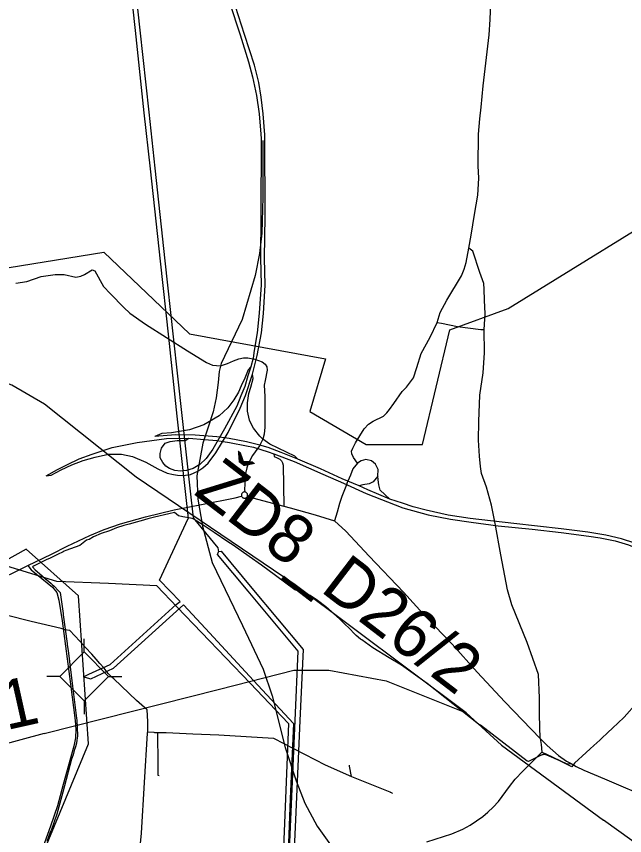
# Model space of a CAD drawing. Extents: x -789162 to -606354, y -1062736 to -945481.
# Drawn here: x -686768 to -684895, y -994659 to -992137 of the extents above; entities that cross this region are included whole.
import ezdxf

# ---------------------------------------------------------------- set-up
doc = ezdxf.new("R2010")
doc.units = 0
for name, color, linetype in [('_SIRSI VZTAHY_CYKLOTRASY MISTNI S', 7, 'Continuous'), ('_SIRSI VZTAHY_ELEKTRICKE VEDENI VN 110 kV S', 7, 'Continuous'), ('_SIRSI VZTAHY_ELEKTRO_ROZVODNA S', 7, 'Continuous'), ('_SIRSI VZTAHY_OP vodnich zdroju II stupne', 7, 'Continuous'), ('_SIRSI VZTAHY_SILNICE I TRIDY_NAVRH', 7, 'Continuous'), ('_SIRSI VZTAHY_SILNICE I TRIDY_STAV', 7, 'Continuous'), ('_SIRSI VZTAHY_SILNICE II TRIDY_STAV', 7, 'Continuous'), ('_SIRSI VZTAHY_SILNICE III TRIDY_STAV', 7, 'Continuous'), ('_SIRSI VZTAHY_VTL PLYNOVOD', 7, 'Continuous'), ('_SIRSI VZTAHY_ZELEZNICE NAVRH', 7, 'Continuous'), ('_SIRSI VZTAHY_ZELEZNICE_NAVRH POPIS', 7, 'Continuous')]:
    doc.layers.add(name, color=color, linetype=linetype)

msp = doc.modelspace()

# ---------------------------------------------------------------- linework, layer by layer
at = {"layer": '_SIRSI VZTAHY_CYKLOTRASY MISTNI S'}
for points in [[(-687456.1, -993024.3), (-687013.2, -992946.4), (-686498.6, -992862.6), (-686235.3, -993114.1), (-685816.3, -993191.9), (-685864.2, -993353.6), (-685690.7, -993455.4), (-685517.1, -993455.4), (-685433.3, -993102.1), (-685253.8, -993036.2), (-684661.3, -992670.9), (-684535.6, -992790.7), (-683781.6, -992335.6), (-683775.6, -992760.8), (-683195.1, -992383.5), (-682889.9, -992994.3), (-682866, -992760.8)], [(-684053.5, -995624.9), (-684491.2, -995009), (-684778.4, -995050.1), (-684949.4, -994827.6), (-685034.9, -995207.5), (-685534.2, -995217.7), (-685623.1, -994998.7), (-686119, -994820.8), (-686426.8, -994858.4), (-686720.9, -994796.8), (-686546.4, -994375.9), (-686577.2, -993920.8), (-686738, -993777.1), (-687381.5, -994136), (-687477.3, -993800.6), (-687483.2, -993028.1)]]:
    msp.add_lwpolyline(points, dxfattribs=at)
at = {"layer": '_SIRSI VZTAHY_ELEKTRICKE VEDENI VN 110 kV S'}
for points in [[(-686349, -990126), (-686423, -990349.7), (-686497.1, -990573.9), (-686557.7, -990757.1), (-686529.4, -991016.9), (-686502.4, -991265.1), (-686475.3, -991514.4), (-686450, -991747.7), (-686425.4, -991973.3), (-686402.7, -992181.3), (-686375.2, -992433.8), (-686356.6, -992606.6), (-686325.5, -992891.3), (-686300.1, -993125.2), (-686273.7, -993367.7), (-686249.4, -993590.9)], [(-686349, -990126), (-686423, -990349.7), (-686497.1, -990573.9), (-686557.7, -990757.1), (-686529.4, -991016.9), (-686502.4, -991265.1), (-686475.3, -991514.4), (-686450, -991747.7), (-686425.4, -991973.3), (-686402.7, -992181.3), (-686375.2, -992433.8), (-686356.6, -992606.6), (-686325.5, -992891.3), (-686300.1, -993125.2), (-686273.7, -993367.7), (-686249.4, -993590.9)], [(-686334.7, -990130.7), (-686408.7, -990354.4), (-686482.9, -990578.6), (-686542.4, -990758.7), (-686514.5, -991015.2), (-686487.5, -991263.5), (-686460.4, -991512.7), (-686435, -991746), (-686410.4, -991971.7), (-686387.8, -992179.6), (-686360.3, -992432.1), (-686341.6, -992605), (-686310.6, -992889.6), (-686285.2, -993123.6), (-686258.8, -993366.1), (-686234.5, -993589.2)], [(-686334.7, -990130.7), (-686408.7, -990354.4), (-686482.9, -990578.6), (-686542.4, -990758.7), (-686514.5, -991015.2), (-686487.5, -991263.5), (-686460.4, -991512.7), (-686435, -991746), (-686410.4, -991971.7), (-686387.8, -992179.6), (-686360.3, -992432.1), (-686341.6, -992605), (-686310.6, -992889.6), (-686285.2, -993123.6), (-686258.8, -993366.1), (-686234.5, -993589.2)], [(-686249.4, -993590.9), (-686239.2, -993682.7)], [(-686234.5, -993589.2), (-686224.3, -993681)], [(-686327.6, -993873), (-686239.2, -993682.7)], [(-686224.3, -993681), (-686147.6, -993772.6), (-686145.8, -993785.2)], [(-686335.6, -993890.5), (-686484.1, -993882.5), (-686643.8, -993877.1), (-686878.4, -993804.9), (-687098.1, -993735.7)], [(-684808.5, -995839.1), (-685038.4, -995799.1), (-685278, -995757.4), (-685386.1, -995738.6), (-685515, -995521.3), (-685674.8, -995252.1), (-685803.8, -995034.6), (-685932.5, -994817.9), (-685922.3, -994585.9), (-685909.9, -994304.2), (-685900.6, -994091.1), (-686054.2, -993906.6), (-686148.6, -993793.5), (-686145.8, -993785.2)], [(-684808.5, -995839.1), (-685038.4, -995799.1), (-685278, -995757.4), (-685386.1, -995738.6), (-685515, -995521.3), (-685674.8, -995252.1), (-685803.8, -995034.6), (-685932.5, -994817.9), (-685922.3, -994585.9), (-685909.9, -994304.2), (-685900.6, -994091.1), (-686054.2, -993906.6), (-686148.6, -993793.5), (-686145.8, -993785.2)], [(-686144.4, -993784.8), (-686137.8, -993783), (-686042.7, -993897), (-685885.3, -994086.1), (-685894.9, -994304.9), (-685907.3, -994586.4), (-685917.4, -994814), (-685790.9, -995026.9), (-685661.9, -995244.4), (-685502.1, -995513.6), (-685376.7, -995725), (-685275.7, -995742.5), (-685035.9, -995784.3), (-684805.8, -995824.3)], [(-686144.4, -993784.8), (-686137.8, -993783), (-686042.7, -993897), (-685885.3, -994086.1), (-685894.9, -994304.9), (-685907.3, -994586.4), (-685917.4, -994814), (-685790.9, -995026.9), (-685661.9, -995244.4), (-685502.1, -995513.6), (-685376.7, -995725), (-685275.7, -995742.5), (-685035.9, -995784.3), (-684805.8, -995824.3)], [(-686335.6, -993890.5), (-686272.8, -993955.9), (-686198.4, -994034), (-686048.5, -994189.7), (-685930.6, -994313.4)], [(-686327.6, -993873), (-686263.8, -993937.8)], [(-686558.6, -994170), (-686558.6, -994169.6), (-686559.2, -994169.6), (-686559.2, -994168.9), (-686544.8, -994162.2), (-686479.6, -994131.8), (-686275.9, -993948), (-686263.8, -993937.8)], [(-686558.6, -994170), (-686558.6, -994169.7), (-686559.2, -994169.7), (-686559.2, -994170.7), (-686557.8, -994170.7), (-686538.5, -994175.9), (-686469.5, -994143), (-686253.7, -993948.4)], [(-686253.7, -993948.4), (-686186.2, -994021.8), (-686037.9, -994181.8), (-685915.3, -994313.6)], [(-685930.6, -994313.4), (-685939.6, -994544.9), (-685950.8, -994822.5), (-685836.9, -995016.8), (-685710.8, -995231.7), (-685573.2, -995464.2), (-685438.6, -995695.3), (-685306.4, -995922.2), (-685024.6, -995974.9), (-684755, -996025.3)], [(-685915.3, -994313.6), (-685924.6, -994545.5), (-685935.6, -994818.7), (-685824, -995009.2), (-685697.8, -995224.1), (-685560.3, -995456.6), (-685425.6, -995687.8), (-685296.9, -995908.7), (-685021.9, -995960.1), (-684752.2, -996010.5)]]:
    msp.add_lwpolyline(points, dxfattribs=at)
at = {"layer": '_SIRSI VZTAHY_ELEKTRO_ROZVODNA S'}
for p, q in [((-686559.2, -994093.6), (-686559.2, -994053.2)), ((-686634.5, -994168.9), (-686559.2, -994093.6)), ((-686559.2, -994093.6), (-686484, -994168.9)), ((-686634.5, -994168.9), (-686674.9, -994168.9)), ((-686559.2, -994244.1), (-686634.5, -994168.9)), ((-686484, -994168.9), (-686559.2, -994244.1)), ((-686484, -994168.9), (-686443.5, -994168.9)), ((-686559.2, -994244.1), (-686559.2, -994284.6))]:
    msp.add_line(p, q, dxfattribs=at)
at = {"layer": '_SIRSI VZTAHY_OP vodnich zdroju II stupne'}
msp.add_lwpolyline([(-684856.5, -994248.7), (-684896.3, -994293.8), (-684916, -994312.7), (-684931.6, -994327.4), (-684947.5, -994342.4), (-684965.4, -994358.8), (-684971.6, -994364.7), (-684990, -994381.5), (-685000.8, -994391.5), (-685013.5, -994402.9), (-685049.3, -994435.8), (-685057.4, -994447.2), (-685086.6, -994432.4), (-685096.7, -994427.8), (-685134.6, -994411.1), (-685136.1, -994410.5), (-685137.7, -994410), (-685139.3, -994409.6), (-685140.9, -994409.4), (-685142.6, -994409.3), (-685144.2, -994409.3), (-685145.8, -994409.5), (-685147.4, -994409.8), (-685149.3, -994410.2), (-685151, -994410.7), (-685152.7, -994411.4), (-685154.3, -994412.2), (-685155.8, -994413.1), (-685191.4, -994430.8), (-685194.9, -994429.2), (-685339.3, -994319.2), (-685345.4, -994316.3), (-685503.2, -994190.7), (-685581.8, -994134.5), (-685620.5, -994111.4), (-685670.4, -994081.1), (-685704.4, -994056.7), (-685708.2, -994053.9), (-685721.4, -994042.4), (-685729.3, -994035.6), (-685740.5, -994023.7), (-685759.8, -994005.2), (-685771.2, -993993.3), (-685782.5, -993983.8), (-685789.2, -993977.5), (-685815, -993954.4), (-685840.7, -993935.5), (-685863.3, -993920.2), (-685889.8, -993908.5), (-685910.7, -993902.6), (-685970.4, -993858.7), (-686013.3, -993826.4), (-686051.4, -993799.6), (-686100.6, -993765.2), (-686116.6, -993754.5), (-686159.5, -993725.8), (-686193, -993703.5), (-686224.1, -993683.5), (-686231.8, -993681.7), (-686255.1, -993677.2), (-686268.9, -993675), (-686280.8, -993664.2), (-686299.2, -993668.3), (-686342.7, -993678.5), (-686363.2, -993684.1), (-686384.2, -993689.5), (-686398.9, -993693.6), (-686402.9, -993694.8), (-686421, -993699.8), (-686437.1, -993704.5), (-686440.4, -993705.5), (-686457, -993710.1), (-686459.4, -993711.2), (-686481.5, -993720.9), (-686506.7, -993728.8), (-686530.4, -993739.3), (-686543.7, -993747.7), (-686552.3, -993749.7), (-686562.7, -993758), (-686572.3, -993765.7), (-686616, -993781), (-686621.4, -993783.6), (-686624.6, -993785.2), (-686641.5, -993793.5), (-686664.3, -993804.6), (-686676.2, -993810.5), (-686715.9, -993829.9), (-686718.7, -993831.3), (-686710.6, -993841), (-686689.6, -993858.7), (-686685.6, -993862.1), (-686662.5, -993881.7), (-686658.1, -993886.2), (-686651.9, -993890.6), (-686638.6, -993905.8), (-686633.5, -993910.5), (-686624.5, -993975.4), (-686624.1, -993978.8), (-686611.9, -994067.1), (-686611.3, -994071.6), (-686608.6, -994089.3), (-686595.1, -994198.9), (-686586, -994272.7), (-686582.9, -994297.2), (-686582.2, -994303.2), (-686582, -994310.8), (-686581.7, -994313.5), (-686581, -994316.7), (-686580.8, -994327.1), (-686580.8, -994329.3), (-686580.4, -994347.4), (-686580.2, -994353.1), (-686582, -994365.3), (-686583.3, -994374.4), (-686586.4, -994385.3), (-686589.8, -994397.1), (-686593.8, -994410.1), (-686598, -994423.7), (-686619.7, -994505.9), (-686624.8, -994525.2), (-686634.5, -994559.2), (-686643.1, -994592.4), (-686660.8, -994642.7), (-686664, -994648.5), (-686674.9, -994676.4)], dxfattribs=at)
at = {"layer": '_SIRSI VZTAHY_SILNICE I TRIDY_NAVRH'}
msp.add_lwpolyline([(-686009, -992519.3), (-686008.8, -992693.9), (-686012.4, -992805), (-686019.8, -992867), (-686033.1, -992934.5), (-686072.5, -993070.3), (-686127.1, -993184), (-686137.7, -993205.4), (-686143.7, -993230), (-686147.2, -993264.3), (-686152.7, -993311.3), (-686161.7, -993354.7), (-686177.9, -993402), (-686193.9, -993451), (-686212.2, -993551.1), (-686209.7, -993623.7), (-686195.4, -993706.4), (-686165.2, -993818.4), (-686071.8, -994012.5), (-686008, -994147), (-685980.1, -994228.6), (-685940.6, -994387.4), (-685906.2, -994489.7), (-685880.1, -994559.2), (-685841.6, -994630.1), (-685780.6, -994715.4)], dxfattribs=at)
at = {"layer": '_SIRSI VZTAHY_SILNICE I TRIDY_STAV'}
for points in [[(-686371.7, -991297.6), (-686361.9, -991326.8), (-686255.6, -991648.6), (-686175.5, -991900.5), (-686079.2, -992193.9), (-686053, -992277.8), (-686041, -992323), (-686028.4, -992380.7), (-686020.2, -992437.3), (-686015.1, -992500.1), (-686014.6, -992512.8)], [(-686002.6, -992506.4), (-686002.8, -992501.9), (-686008.2, -992437.6), (-686014.5, -992385.9), (-686022, -992341.3), (-686034.7, -992287.1), (-686065.4, -992192.7), (-686158.5, -991904.8), (-686243.5, -991648.6), (-686361.2, -991289.1)], [(-686040.9, -993238.6), (-686027.2, -993181.1), (-686013.8, -993111.8), (-686007.3, -993051.8), (-686001.8, -992964.6), (-686003.8, -992881.1), (-686002.4, -992753.1), (-686002.6, -992506.4)], [(-686014.6, -992512.8), (-686015.3, -992752.6), (-686016.6, -992880.6), (-686014.8, -992964.1), (-686020.2, -993051.2), (-686026.6, -993111.2), (-686036, -993165.4), (-686039.5, -993189.2), (-686046, -993216)], [(-686046, -993216), (-686054.3, -993224.8), (-686064.4, -993251.4), (-686075.7, -993275), (-686084.3, -993294.3), (-686098.4, -993317.4), (-686116.8, -993341.7), (-686144.2, -993367.2), (-686191.2, -993394.2), (-686235.1, -993410), (-686290, -993419.1), (-686320.7, -993421.7), (-686341.9, -993430.3)], [(-686046, -993216), (-686055.2, -993244), (-686065.2, -993276.3), (-686077, -993305.2), (-686089.3, -993337.2), (-686126.8, -993406.9), (-686163.5, -993469), (-686184.1, -993498.3), (-686203.7, -993516.6), (-686223.4, -993528.8), (-686244.8, -993535.4), (-686262.3, -993536.7), (-686280.2, -993535), (-686296.3, -993528.8), (-686308.1, -993521.4), (-686317.7, -993510.9), (-686325.2, -993496.5), (-686325.6, -993482.5), (-686321.7, -993465.9), (-686310.3, -993450.6), (-686294.6, -993445.4), (-686273.2, -993443.2), (-686248.7, -993442.3), (-686236.9, -993436)], [(-686676.8, -993551.1), (-686660.9, -993549.2), (-686630.2, -993533.4), (-686597.4, -993518), (-686562.5, -993504.8), (-686526, -993493.7), (-686484.9, -993484.8), (-686444.2, -993484.8), (-686410.1, -993491.8), (-686369.4, -993509.1), (-686332.8, -993529.9), (-686304, -993542.8), (-686284.7, -993547.8), (-686271.8, -993549.8), (-686255.9, -993550.8), (-686232.1, -993547.3), (-686209.8, -993536.9), (-686194.4, -993526.5), (-686178.1, -993512.1), (-686153.8, -993480.9), (-686115.7, -993417.9), (-686079.5, -993343.1), (-686062.6, -993303.9), (-686040.9, -993238.6)], [(-685901.2, -993500.5), (-685911.1, -993491), (-685987.3, -993454.5), (-686008.8, -993438.5), (-686018.5, -993429.9), (-686038.5, -993405.2), (-686044.1, -993394), (-686050.8, -993379.8), (-686056.2, -993352), (-686056.1, -993327), (-686052.1, -993298.6), (-686046, -993278.1), (-686039.5, -993251.9), (-686040.9, -993238.6)], [(-686676.8, -993551.1), (-686641.9, -993532.3), (-686610.7, -993516.4), (-686575.2, -993499.5), (-686535.1, -993484.6), (-686472.9, -993464.3), (-686395.8, -993448.7), (-686306, -993436.8), (-686236.9, -993436)], [(-685901.2, -993500.5), (-685953, -993480), (-685992.9, -993464.2), (-686018.6, -993456.9), (-686038.8, -993451.5), (-686059.6, -993447.2), (-686112.7, -993436.8), (-686151.4, -993431.3), (-686217.5, -993426.5), (-686278.2, -993424.9), (-686341.9, -993430.3)], [(-686236.9, -993436), (-686188.4, -993439.7), (-686150.9, -993443.2), (-686112.2, -993448.6), (-686059.1, -993459.1), (-686038.2, -993463.4), (-685993.2, -993477.4), (-685975.8, -993483.8)], [(-685975.8, -993483.8), (-685974.2, -993492.1), (-685964.7, -993496.6), (-685957.3, -993500.6), (-685952.1, -993505.3), (-685948.6, -993511.3), (-685946.8, -993518.3), (-685944.8, -993645.2)], [(-685975.8, -993483.8), (-685913, -993507.3), (-685824.2, -993546.7), (-685760.4, -993574.2), (-685691.4, -993605.5), (-685578.2, -993649.7), (-685499.7, -993671.6), (-685431.1, -993685.2), (-685368.2, -993693.9), (-685284.4, -993705.5), (-685179.6, -993715.4), (-685090.1, -993725.9), (-685004.9, -993736.9), (-684970.1, -993742.5), (-684924.8, -993751.6), (-684883.1, -993764), (-684843.6, -993779.9)], [(-685712.9, -993582.1), (-685764.8, -993560.5), (-685831.6, -993529.9), (-685901.2, -993500.5)], [(-685718.2, -993512.1), (-685731.7, -993530), (-685739.2, -993549.8), (-685747.3, -993567.8), (-685749.1, -993571.8), (-685752.1, -993579.5), (-685765.8, -993614.9), (-685773.2, -993636.6), (-685780.8, -993663.6), (-685788.2, -993690.4)], [(-685654.7, -993552.8), (-685654.2, -993531.9), (-685662.2, -993516), (-685675.1, -993505.8), (-685691.9, -993501.1), (-685706.4, -993505), (-685718.2, -993512.1)], [(-685654.7, -993552.8), (-685669.1, -993569.8), (-685681.4, -993575.7), (-685700.9, -993579.4), (-685712.9, -993582.1)], [(-685617.7, -993623.2), (-685647.7, -993595.4), (-685652.2, -993579), (-685653.7, -993564.1), (-685654.7, -993552.8)], [(-685617.7, -993623.2), (-685685.9, -993594.2), (-685712.9, -993582.1)], [(-684753.4, -993814.1), (-684793.9, -993790.7), (-684827.8, -993773.7), (-684864.1, -993758.9), (-684904.3, -993745.1), (-684952.7, -993733.9), (-685008.2, -993725.1), (-685090.2, -993714.3), (-685236.5, -993697.9), (-685371, -993682.7), (-685438.3, -993672.8), (-685506.2, -993657.6), (-685546.8, -993646.9), (-685578.7, -993635.9), (-685617.7, -993623.2)]]:
    msp.add_lwpolyline(points, dxfattribs=at)
at = {"layer": '_SIRSI VZTAHY_SILNICE II TRIDY_STAV'}
for points in [[(-685154.9, -994359.6), (-685151.8, -994378.2), (-685150.6, -994402.3)], [(-685504.3, -994677.9), (-685427, -994653), (-685393.8, -994638.8), (-685370.9, -994626.6), (-685351.8, -994613.6), (-685332, -994599.9), (-685316.7, -994586.4), (-685299.5, -994571), (-685283.3, -994553.8), (-685250.1, -994508.1), (-685232.5, -994484.8), (-685208.2, -994460.8), (-685150.6, -994402.3)], [(-685150.6, -994402.3), (-685137.4, -994407), (-685073.2, -994437.4), (-685060.1, -994436.9)], [(-685060.1, -994436.9), (-685044.1, -994446.1), (-685020.3, -994457.8), (-684956.8, -994484.5), (-684808.4, -994547.5), (-684732.2, -994580.6), (-684601.2, -994635.3), (-684560.5, -994651.6)]]:
    msp.add_lwpolyline(points, dxfattribs=at)
at = {"layer": '_SIRSI VZTAHY_SILNICE III TRIDY_STAV'}
for points in [[(-685374.5, -992850.3), (-685367.7, -992811.1), (-685357.2, -992747.2), (-685347, -992687.4), (-685344.1, -992635.2), (-685345.7, -992597), (-685345.2, -992499.6), (-685340.9, -992452.7), (-685336.8, -992416.6), (-685330.7, -992351.2), (-685312.3, -992194.3), (-685309.7, -992146.9), (-685307.5, -992094.3)], [(-685472.9, -993079.2), (-685463.5, -993048.4), (-685442.9, -993010.4), (-685397.9, -992935.9), (-685389, -992915.9), (-685382.8, -992895.1), (-685374.5, -992850.3)], [(-685327.8, -993101.4), (-685325.1, -993052.4), (-685326.7, -993011), (-685328.1, -992977.1), (-685328.9, -992959.2), (-685341.5, -992925.2), (-685363, -992860.3), (-685374.5, -992850.3)], [(-686770.1, -992958.3), (-686735.5, -992953.5), (-686692, -992938.3), (-686648.9, -992932), (-686620.9, -992932.2), (-686585.2, -992939.8), (-686569.5, -992937.3), (-686558, -992932.2), (-686534.6, -992917.9), (-686526.8, -992920.9), (-686499.7, -992968.3), (-686478.3, -992991.4), (-686436.8, -993033.9), (-686418.8, -993050.8), (-686370.8, -993085), (-686241.6, -993166.8), (-686182.5, -993202.8), (-686164.5, -993211.2), (-686139.5, -993213), (-686117.9, -993206.1), (-686100, -993197.6), (-686083.4, -993191.4), (-686068.8, -993188.4), (-686055.2, -993188.4), (-686033.8, -993192.8), (-686010.9, -993200.5), (-686001.8, -993207.5), (-685997, -993216.4), (-685995.8, -993226.5), (-686002.2, -993257.8), (-686004.8, -993272.9), (-686002.8, -993306.9), (-686003, -993401.6), (-686005.4, -993423.6), (-686008.8, -993438.5), (-686019.9, -993459.4), (-686041.5, -993489.1), (-686054.6, -993514.9), (-686058.6, -993527.2), (-686062.7, -993543.8), (-686065.3, -993593.5), (-686065.2, -993601.1)], [(-685718.2, -993512.1), (-685729.8, -993495.4), (-685735.7, -993483.8), (-685736, -993475.2), (-685732.2, -993466.2), (-685723.4, -993449.9), (-685696.9, -993406.9), (-685683.4, -993392.9), (-685669.1, -993382.8), (-685637.6, -993367.5), (-685627.6, -993357.7), (-685618.7, -993347.8), (-685605.9, -993329.1), (-685580.2, -993291.7), (-685566.8, -993278.9), (-685544.8, -993250.1), (-685535, -993218.3), (-685521.7, -993175), (-685494.3, -993124.6), (-685472.9, -993079.2)], [(-685472.9, -993079.2), (-685458.9, -993082.1), (-685409.5, -993091.7), (-685337.6, -993100.9), (-685327.8, -993101.4)], [(-685154.9, -994359.6), (-685156.8, -994287.1), (-685157, -994235.2), (-685160.2, -994163.4), (-685195.2, -994064.9), (-685242.1, -993948.4), (-685255.5, -993902.5), (-685276.3, -993794.6), (-685294, -993697.9), (-685305.6, -993642), (-685320.6, -993586.2), (-685335.8, -993544.3), (-685339, -993523.1), (-685341.7, -993490.9), (-685344.7, -993441.8), (-685344.4, -993384.7), (-685341.2, -993303.7), (-685330.7, -993234.8), (-685326.7, -993173.1), (-685327.8, -993101.4)], [(-686732.7, -993827.1), (-686660.4, -993792.7), (-686611.9, -993768.2), (-686541.9, -993735.5), (-686497.9, -993716.7), (-686447.1, -993699.6), (-686370.4, -993677.5), (-686282.2, -993656.1), (-686198.2, -993640.1), (-686094, -993618.7), (-686074.6, -993613.9)], [(-686065.2, -993601.1), (-686066.8, -993601.2), (-686068.3, -993601.5), (-686069.7, -993602.1), (-686071.1, -993602.9), (-686072.3, -993603.9), (-686073.3, -993605), (-686074.1, -993606.3), (-686074.7, -993607.8), (-686075.1, -993609.3), (-686075.2, -993610.9), (-686075, -993612.4), (-686074.6, -993613.9)], [(-686074.6, -993613.9), (-686073.9, -993615.4), (-686073, -993616.7), (-686071.9, -993617.9), (-686070.6, -993618.9), (-686069.1, -993619.6), (-686067.6, -993620.1), (-686066, -993620.3), (-686064.3, -993620.2), (-686062.7, -993619.8), (-686061.2, -993619.2), (-686059.9, -993618.4), (-686058.6, -993617.3), (-686057.6, -993616), (-686056.8, -993614.6)], [(-686056.8, -993614.6), (-686056.3, -993613.1), (-686056.1, -993611.6), (-686056, -993610), (-686056.3, -993608.5), (-686056.7, -993607), (-686057.5, -993605.7), (-686058.4, -993604.4), (-686059.5, -993603.3), (-686060.8, -993602.4), (-686062.2, -993601.8), (-686063.7, -993601.3), (-686065.2, -993601.1)], [(-686056.8, -993614.6), (-685944.8, -993645.2)], [(-685944.8, -993645.2), (-685924.7, -993650.4), (-685847.8, -993671.1), (-685788.2, -993690.4)], [(-685788.2, -993690.4), (-685754.1, -993721.3), (-685682.1, -993798.9), (-685576.2, -993909.6), (-685506.8, -993986.4), (-685426.2, -994069.3), (-685349.3, -994155.6), (-685264.4, -994247), (-685154.9, -994359.6)], [(-687415.4, -993905.3), (-687401.9, -993933.1), (-687390.1, -993976), (-687372.2, -994086.1), (-687367.1, -994104.2), (-687359.1, -994115.2), (-687347.9, -994119.3), (-687328.4, -994116), (-687285, -994095.5), (-687158.7, -994034.9), (-686846.1, -993882.8), (-686732.7, -993827.1)], [(-686732.7, -993827.1), (-686723, -993841.3), (-686657.3, -993894.6), (-686643.8, -993911), (-686637.1, -993934.3), (-686627.3, -993998.1), (-686601.6, -994192.4), (-686587.5, -994304.5), (-686585.5, -994332.7), (-686586.5, -994357.5), (-686591.6, -994383.2), (-686623.6, -994501.3), (-686642, -994566.9), (-686662.8, -994629.4), (-686695.3, -994718.2), (-686713.1, -994769.8), (-686740.6, -994860.1)], [(-685154.9, -994359.6), (-685133.6, -994381.6), (-685099.2, -994412), (-685074.3, -994429.2), (-685060.1, -994436.9)]]:
    msp.add_lwpolyline(points, dxfattribs=at)
at = {"layer": '_SIRSI VZTAHY_VTL PLYNOVOD'}
for points in [[(-686363.7, -994339.2), (-686363.9, -994322.3), (-686363, -994307.5), (-686365, -994271.9), (-686397.9, -994242.9), (-686468.5, -994176.4), (-686472.9, -994172.3), (-686472.9, -994172.2), (-686473.9, -994171.3), (-686485.5, -994159.4), (-686498.1, -994143.7), (-686510.7, -994129.1), (-686522.2, -994115.7), (-686535.7, -994100.8), (-686554.9, -994079.8), (-686572.8, -994060.6), (-686603.2, -994027.9), (-686618.9, -994025.1), (-686630.3, -994021.8), (-686630.6, -994021.7), (-686722.3, -993999.6), (-686800, -993980.8), (-686907.1, -993952.3), (-686912.1, -993943.5)], [(-686389.8, -994763.8), (-686389.9, -994725.1), (-686383, -994651.6), (-686373.3, -994494.9), (-686364, -994343.7), (-686364, -994343.6), (-686364, -994342.8), (-686363.7, -994339.2)], [(-686363.7, -994339.2), (-686345.2, -994340.8), (-686342.9, -994341), (-686342.4, -994341.1), (-686342.1, -994341.1), (-686341.6, -994341.1), (-686333.8, -994341.3)], [(-686333.8, -994341.3), (-686333.8, -994342), (-686333.8, -994342.3), (-686333.8, -994343.9), (-686333.9, -994344.5), (-686333.9, -994344.8), (-686333, -994437.3), (-686332.4, -994473.1), (-686328.4, -994473.3), (-686328.3, -994473.3)], [(-686333.8, -994341.3), (-686333.2, -994341.3), (-686332.8, -994341.3), (-686332, -994341.3), (-686331.7, -994341.3), (-686306.5, -994341.2), (-686224.6, -994345.8), (-686144.9, -994348.4), (-685976.6, -994358.9), (-685817, -994441), (-685736.1, -994476.4)], [(-685736.1, -994476.4), (-685742, -994444.6), (-685742.2, -994443.3), (-685742.5, -994441.7)], [(-685736.1, -994476.4), (-685617.9, -994523.9), (-685617.7, -994524.5), (-685617.6, -994525), (-685617.1, -994525.2), (-685616.3, -994525.5), (-685612.2, -994527.2), (-685611.6, -994527.4), (-685610.6, -994527.8), (-685610.4, -994527.9), (-685609.8, -994528.1), (-685609.6, -994528.1)]]:
    msp.add_lwpolyline(points, dxfattribs=at)
at = {"layer": '_SIRSI VZTAHY_ZELEZNICE NAVRH'}
msp.add_line((-685274.5, -994380.1), (-684960.1, -994611.1), dxfattribs=at)
for points in [[(-685383.4, -994281.2), (-685910.1, -993887.2), (-686398.9, -993555.2), (-686681.4, -993331.1), (-686781.8, -993272.8), (-686860.3, -993242.4), (-686916, -993224.6), (-687088.2, -993222.1), (-687214.8, -993222.1), (-687379.4, -993222.1), (-687493.4, -993209.4), (-687589.6, -993186.6), (-687645.3, -993133.4), (-687703.6, -993065), (-687716.2, -992988.9), (-687728.9, -992867.3), (-687706.1, -992798.9)], [(-686682.5, -994344.6), (-686143.1, -994207.8), (-685913.3, -994149.5), (-685806.3, -994149.5), (-685629, -994182.4), (-685383.4, -994281.2), (-685274.5, -994380.1)], [(-686682.5, -994344.6), (-687485.4, -994561.6), (-688457.9, -994794.7), (-689372.2, -995027.4)], [(-678700.4, -1001638.9), (-678966.7, -1001313.2), (-679414.9, -1000616.3), (-679595.9, -1000469.8), (-679806.1, -1000218.9), (-680055.6, -999559.5), (-680488.7, -998799.3), (-680595, -998558.5), (-680919.2, -998208.8), (-682198.1, -996934.1), (-682960.3, -996371.5), (-683206, -996232.1), (-683568.1, -996059.8), (-683785.9, -995930.6), (-683950.5, -995730.4), (-684191.1, -995360.4), (-684294.9, -995238.7), (-684753.3, -994759.8), (-684960.1, -994611.1)]]:
    msp.add_lwpolyline(points, dxfattribs=at)

# ---------------------------------------------------------------- texts
at = {"layer": '_SIRSI VZTAHY_ZELEZNICE_NAVRH POPIS'}
for s, rotation, p in [('ŽD8_D26/2', 322.5332, (-686225.1, -993606.2)), ('ŽD8_D26/1', 12.6033, (-687691.8, -994534.2))]:
    msp.add_text(s, height=150, rotation=rotation, dxfattribs=at).set_placement(p)

doc.saveas('drawing.dxf')
